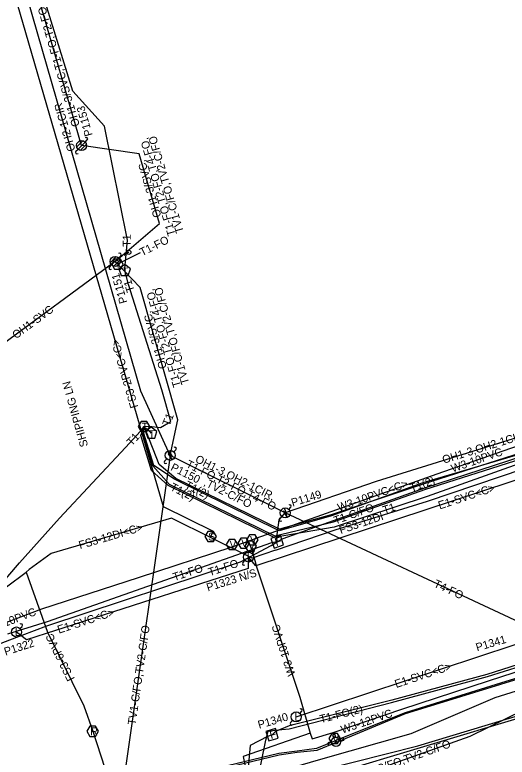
# Model space of a CAD drawing. Extents: x 2336688 to 2352634, y 362473 to 369571.
# Drawn here: x 2346759.7 to 2347005.5, y 367179.3 to 367550.3 of the extents above; entities that cross this region are included whole.
import ezdxf

# ---------------------------------------------------------------- set-up
doc = ezdxf.new("R2010")
doc.units = 0
for name, color, linetype in [('RD_EX_DV_Prop', 7, 'Continuous'), ('RD_EX_DV_TX_Prop', 7, 'Continuous'), ('RD_EX_RW', 7, 'Continuous'), ('RD_EX_RW_TX', 7, 'Continuous'), ('RD_HC_Data_Tic', 7, 'Continuous'), ('RD_PD_CstnLmt', 7, 'Continuous'), ('RD_PD_Final_TrvlWay', 7, 'Continuous'), ('RD_PD_PatLn4', 7, 'Continuous'), ('RD_SHT_ShtClip', 7, 'Continuous'), ('RD_Sketch1', 7, 'Continuous'), ('RD_Sketch2', 7, 'Continuous'), ('RD_Sketch5', 7, 'Continuous'), ('RD_TX_Misc1', 7, 'Continuous')]:
    doc.layers.add(name, color=color, linetype=linetype)

# ---------------------------------------------------------------- blocks, each defined once
blk = doc.blocks.new('GW')
at = {"layer": 'RD_HC_Data_Tic'}
blk.add_line((0, 0), (0, 5), dxfattribs=at)
blk.add_circle((0, 0), 2, dxfattribs=at)

msp = doc.modelspace()

# ---------------------------------------------------------------- linework, layer by layer
at = {"layer": 'RD_EX_RW_TX'}
msp.add_line((2346913.35, 367169.48), (2347148.27, 367240), dxfattribs=at)
for points in [[(2346827.77, 367341.15), (2346827.34, 367341.7), (2346825.07, 367343.48), (2346824.21, 367344.56), (2346824.21, 367344.56), (2346826.62, 367344.73), (2346832.44, 367344.01), (2346837.57, 367347.11), (2346833.13, 367362.89), (2346816.44, 367415.45), (2346815.1, 367420.66), (2346814.52, 367422.45), (2346814.54, 367423.44), (2346815.97, 367437.64), (2346804.36, 367494.65), (2346788.63, 367512.17), (2346772.74, 367563.49)], [(2347493.21, 367479.93), (2347455.71, 367473.66), (2347452.74, 367474.1), (2347448.74, 367473.85), (2347412.51, 367459.94), (2347396.43, 367453.77), (2347382.64, 367448.58), (2347379.12, 367448.82), (2347347.7, 367441.05), (2347301.35, 367428.58), (2347253.11, 367413.66), (2347204.34, 367396.75), (2347168.08, 367381.62), (2347139.54, 367369.91), (2347109.42, 367360.33), (2347060.14, 367343.81), (2347012.82, 367329.5), (2346964.23, 367313.72), (2346893.43, 367288.42), (2346890.71, 367286.97), (2346887.9, 367286.45), (2346775.81, 367246.88), (2346756.05, 367240.68)], [(2347493.07, 367480.59), (2347455.62, 367474.3), (2347452.74, 367474.1), (2347450.17, 367472.02), (2347413.02, 367459.45), (2347396.97, 367451.28), (2347348.05, 367437.46), (2347302.76, 367423.98), (2347255.28, 367408.11), (2347207.74, 367387.96), (2347168.62, 367376.63), (2347134.49, 367365.89), (2347110.11, 367358.5), (2347060.95, 367341.47), (2347013.68, 367326.75), (2346965.57, 367309.6), (2346919.17, 367294.2), (2346889.18, 367289.05), (2346836.21, 367315.04), (2346827.9, 367322.52), (2346822.65, 367340.13), (2346824.21, 367344.56)], [(2347493.75, 367473.66), (2347444.81, 367465.06), (2347396.07, 367455.9), (2347345.96, 367442.69), (2347300.78, 367430.21), (2347252.72, 367414.9), (2347203.98, 367399.02), (2347167.78, 367385.01), (2347137.95, 367372.86), (2347109.32, 367361.19), (2347059.71, 367345.57), (2347012.57, 367330.88), (2346963.45, 367316.33), (2346917.8, 367299.85), (2346891.73, 367292.36), (2346839.33, 367318.15), (2346829.05, 367325.03), (2346824.09, 367341.03), (2346824.21, 367344.56)], [(2347493.77, 367474.07), (2347444.64, 367465.68), (2347395.98, 367456.43), (2347345.81, 367443.17), (2347300.67, 367430.69), (2347252.46, 367415.35), (2347204.25, 367399.86), (2347167.66, 367385.47), (2347137.74, 367373.17), (2347109.3, 367361.85), (2347059.64, 367346.11), (2347012.51, 367331.46), (2346963.58, 367315.78), (2346917.62, 367300.41), (2346891.78, 367293.28), (2346839.99, 367318.61), (2346831.68, 367325.52), (2346825.4, 367341.75), (2346824.21, 367344.56)], [(2346822.31, 367431.36), (2346811.94, 367426.18), (2346810.92, 367425.75), (2346809.69, 367427.05)], [(2346744.36, 367255.92), (2346762.03, 367276.39), (2346781.92, 367298.77), (2346814.85, 367333.98), (2346822.42, 367342.26), (2346824.21, 367344.56), (2346823.39, 367341.4), (2346828.52, 367324.89), (2346836.66, 367315.73), (2346889.46, 367289.94), (2346918.72, 367296.97), (2346964.46, 367313.14), (2347013.05, 367328.63), (2347060.47, 367342.93), (2347109.88, 367359.54), (2347134.28, 367367.62), (2347132.27, 367372.32), (2347131.88, 367373.69), (2347132.25, 367375.15), (2347127.72, 367400.1)], [(2346929.43, 366898.3), (2346926.24, 366950.27), (2346914.94, 366994.66), (2346903.95, 367048.72), (2346891.88, 367094.98), (2346882.43, 367148.75), (2346880.23, 367164.03), (2346885.05, 367187.76), (2346886.25, 367192.23), (2346889.58, 367192.85), (2346896.67, 367193.51), (2346947.77, 367206.59), (2346995.79, 367219.64), (2347046.69, 367235.53), (2347089.94, 367248.15), (2347136.19, 367262.43), (2347184.88, 367278.93), (2347230.19, 367297.47), (2347271.77, 367311.28), (2347325.01, 367320.63), (2347375.99, 367328.45), (2347424.9, 367338.06), (2347468.18, 367347.3), (2347525.21, 367359.4)], [(2346729.92, 367125.44), (2346760.09, 367132.46), (2346822.83, 367150.8), (2346847.92, 367159.43), (2346911.38, 367177.91), (2346957.67, 367191.14), (2346999.5, 367209.08), (2347049.12, 367224.56), (2347093.92, 367240.35), (2347120.7, 367252.77), (2347143.99, 367255.5), (2347186.71, 367269.91), (2347236.58, 367285.94), (2347255.06, 367289.24), (2347276.57, 367291.67), (2347281.58, 367292.99), (2347300.77, 367298.26), (2347328.04, 367305.43), (2347378.49, 367318.88), (2347428.36, 367324.58), (2347471.76, 367333.48), (2347528.47, 367342.27)], [(2346897.18, 367161.87), (2346897.33, 367167.15), (2346913.45, 367172.96), (2346960.85, 367184.91), (2347003.36, 367197.72), (2347054.81, 367213.14), (2347089.91, 367226.4), (2347147.29, 367244.91), (2347193.34, 367259.48), (2347243.62, 367272.38), (2347257.76, 367276.24), (2347278.69, 367281.44), (2347302.95, 367288.88), (2347331.85, 367293.13), (2347381.23, 367305.16), (2347429.75, 367317.72), (2347473.23, 367326.64), (2347527.97, 367334.66)], [(2346386.07, 367172.12), (2346435.22, 367175.26), (2346485.78, 367178.87), (2346532.3, 367185.17), (2346581.16, 367192.44), (2346634.62, 367203.07), (2346681.71, 367213.65), (2346729.26, 367227.27), (2346757.13, 367237.94), (2346775.57, 367244.97), (2346872.31, 367276.87), (2346887.68, 367285.05), (2346890.71, 367286.97), (2346890.49, 367289.26), (2346891.73, 367297.92), (2346894.69, 367301.37)], [(2347184.08, 367281.81), (2347138.56, 367267.72), (2347089.38, 367252.03), (2347046.03, 367236.73), (2346995.36, 367220.65), (2346947.88, 367207.83), (2346896.65, 367195.02), (2346889.86, 367192.06), (2346888.13, 367190.49), (2346885.89, 367189.55), (2346877.25, 367185.04), (2346875.24, 367162.99), (2346879.34, 367145.21), (2346889.15, 367095.18), (2346897.75, 367046.5), (2346908.64, 366996.35), (2346918.58, 366948.75), (2346927.75, 366898.93)], [(2347187.63, 367266.43), (2347137.4, 367253.23), (2347093.35, 367238.65), (2347047.24, 367230.28), (2346997.39, 367214.83), (2346954.54, 367201.39), (2346927.39, 367190.56), (2346910.36, 367183.58), (2346900.58, 367182.36), (2346891.43, 367181.19), (2346845.03, 367169.9), (2346819.99, 367162.67), (2346802.3, 367157.83), (2346797.35, 367156.24), (2346793.14, 367153.5), (2346783.01, 367146.37), (2346758.96, 367136.25)], [(2346759.16, 367135.67), (2346783.33, 367145.57), (2346793.56, 367152.89), (2346797.35, 367156.24), (2346802.42, 367157.05), (2346820.18, 367162.16), (2346845.16, 367169.26), (2346891.6, 367180.39), (2346900.69, 367181.78), (2346910.69, 367182.74), (2346927.88, 367189.94), (2346954.81, 367201.03), (2346997.5, 367214.34), (2347047.41, 367229.71), (2347093.48, 367238.02), (2347137.76, 367252.45), (2347187.57, 367265.92)]]:
    msp.add_lwpolyline(points, dxfattribs=at)
for points in [[(2346813.81, 367425.75), (2346812.37, 367428.25), (2346809.48, 367428.25), (2346808.04, 367425.75), (2346809.48, 367423.25), (2346812.37, 367423.25)], [(2346814.52, 367425.45), (2346811.67, 367423.38), (2346812.76, 367420.02), (2346816.28, 367420.02), (2346817.37, 367423.38)], [(2346827.1, 367344.56), (2346825.66, 367347.06), (2346822.77, 367347.06), (2346821.33, 367344.56), (2346822.77, 367342.06), (2346825.66, 367342.06)], [(2346827.77, 367344.15), (2346824.92, 367342.07), (2346826.01, 367338.72), (2346829.53, 367338.72), (2346830.62, 367342.07)], [(2346892.3, 367290.13), (2346887.56, 367288.56), (2346889.12, 367283.81), (2346893.87, 367285.38)], [(2346889.79, 367193.61), (2346885.01, 367192.15), (2346886.47, 367187.37), (2346891.25, 367188.83)]]:
    msp.add_lwpolyline(points, close=True, dxfattribs=at)
at = {"layer": 'RD_HC_Data_Tic'}
for p, q in [((2346790.59, 367484.3), (2346793.65, 367487.36)), ((2346791.23, 367483.18), (2346794.77, 367486.71)), ((2346794.77, 367486.71), (2346795.83, 367487.77)), ((2346790.17, 367482.11), (2346791.23, 367483.18)), ((2346792.35, 367482.53), (2346795.42, 367485.59)), ((2346807.27, 367426.4), (2346810.33, 367429.46)), ((2346807.92, 367425.28), (2346811.45, 367428.81)), ((2346809.04, 367424.63), (2346812.1, 367427.69)), ((2346811.45, 367428.81), (2346812.52, 367429.88)), ((2346806.86, 367424.22), (2346807.92, 367425.28)), ((2346839.05, 367331.88), (2346840.11, 367332.95)), ((2346834.46, 367327.29), (2346835.52, 367328.35)), ((2346896.46, 367303.14), (2346897.52, 367304.2)), ((2346891.86, 367298.54), (2346892.92, 367299.61)), ((2346878.11, 367281.07), (2346879.17, 367282.13)), ((2346873.51, 367276.47), (2346874.57, 367277.54)), ((2346762.2, 367243.61), (2346763.26, 367244.67)), ((2346901.94, 367201.18), (2346903, 367202.24)), ((2346897.34, 367196.59), (2346898.4, 367197.65))]:
    msp.add_line(p, q, dxfattribs=at)
for points in [[(2346836.89, 367332.13), (2346837.72, 367330.11), (2346836.26, 367330.91), (2346838.14, 367328.23), (2346838.14, 367328.23), (2346836.94, 367330.33), (2346838.32, 367329.53)], [(2346894.29, 367303.38), (2346895.12, 367301.37), (2346893.66, 367302.17), (2346895.54, 367299.49), (2346895.54, 367299.49), (2346894.34, 367301.58), (2346895.72, 367300.78)]]:
    msp.add_lwpolyline(points, close=True, dxfattribs=at)
for centre in [(2346793, 367484.94), (2346809.69, 367427.05), (2346837.29, 367330.12), (2346894.69, 367301.37), (2346876.34, 367279.3), (2346760.44, 367241.84), (2346900.17, 367199.42)]:
    msp.add_circle(centre, 2.5, dxfattribs=at)
for centre, start, end in [((2346795.3, 367488.3), 315, 135), ((2346790.7, 367481.58), 135, 315), ((2346811.99, 367430.41), 315, 135), ((2346807.39, 367423.69), 135, 315), ((2346839.58, 367333.48), 315, 135), ((2346834.99, 367326.76), 135, 315), ((2346896.99, 367304.73), 315, 135), ((2346892.39, 367298.01), 135, 315), ((2346878.64, 367282.66), 315, 135), ((2346874.04, 367275.94), 135, 315), ((2346762.73, 367245.2), 315, 135), ((2346902.47, 367202.77), 315, 135), ((2346897.87, 367196.06), 135, 315)]:
    msp.add_arc(centre, 0.75, start, end, dxfattribs=at)
at = {"layer": 'RD_PD_Final_TrvlWay'}
for points in [[(2347365.04, 367648.59), (2347375.04, 367646.81), (2347420.85, 367453.86), (2347411.66, 367432.11), (2347408.65, 367425.96), (2347247.09, 367389.8), (2347245.57, 367389.37), (2347243.03, 367393.87), (2347242.83, 367388.6), (2347145.71, 367361.39), (2347142.58, 367366.06), (2347142.34, 367360.37), (2347024.46, 367322.51), (2347021.03, 367327.02), (2347021.01, 367321.39), (2346880.04, 367274.9), (2346876.34, 367279.3), (2346876.12, 367273.62), (2346794.47, 367247.23), (2346765.54, 367237.88), (2346760.44, 367241.84)], [(2346900.17, 367199.42), (2347008.96, 367235.37), (2347049.36, 367249.06), (2347056.78, 367227.15), (2347058.34, 367224.76), (2347058.11, 367227.6), (2347050.69, 367249.51), (2347105.72, 367268.16), (2347228.62, 367304.26)]]:
    msp.add_lwpolyline(points, dxfattribs=at)
at = {"layer": 'RD_SHT_ShtClip'}
for p, q in [((2346793, 367484.94), (2346749.05, 367636.56)), ((2346809.69, 367427.05), (2346738.38, 367374.51)), ((2346837.29, 367330.12), (2346809.48, 367136.35)), ((2346894.69, 367301.37), (2346837.29, 367330.12)), ((2347058.34, 367224.76), (2346894.69, 367301.37))]:
    msp.add_line(p, q, dxfattribs=at)
for points in [[(2346837.29, 367330.12), (2346822.52, 367362.29), (2346753.65, 367601.46), (2346749.05, 367636.56)], [(2346809.69, 367427.05), (2346831.86, 367445.93), (2346821.82, 367480.76), (2346793, 367484.94)], [(2346837.29, 367330.12), (2346841.01, 367347.81), (2346822.17, 367413.97), (2346809.69, 367427.05)], [(2347135.6, 367376.27), (2347089.3, 367363.5), (2346940.06, 367317.1), (2346894.69, 367301.37)], [(2346809.48, 367136.35), (2346886.82, 367154.19), (2346987.08, 367189.8), (2347058.34, 367224.76)]]:
    msp.add_lwpolyline(points, dxfattribs=at)
at = {"layer": 'RD_Sketch2'}
for p, q in [((2346880.2, 367288.69), (2346970.59, 367320.92)), ((2346919.46, 367190.72), (2346918.36, 367190.36)), ((2346918.36, 367190.36), (2346918.82, 367188.96)), ((2346919.93, 367189.3), (2346919.46, 367190.72)), ((2346917.72, 367186.93), (2346916.01, 367186.37)), ((2346916.01, 367186.37), (2346916.37, 367185.27)), ((2346916.37, 367185.27), (2346918.04, 367185.82)), ((2346923.69, 367188.9), (2346921.92, 367188.32)), ((2346922.33, 367187.23), (2346924.05, 367187.8)), ((2346924.05, 367187.8), (2346923.69, 367188.9))]:
    msp.add_line(p, q, dxfattribs=at)
for points in [[(2346907.18, 367191.36), (2346908.2, 367188.48), (2346918.67, 367191.57), (2346952.96, 367203.21), (2346996.26, 367217.42), (2347046.54, 367233.83), (2347089.24, 367248.48), (2347137.8, 367263.72), (2347185.19, 367277.87), (2347233.41, 367292.66), (2347283.51, 367309.44), (2347303.65, 367314.93), (2347326.25, 367319.14), (2347377.74, 367324.63), (2347405.39, 367327.95), (2347438.97, 367330.87), (2347470.35, 367337.23), (2347531.2, 367351.47)], [(2346970.59, 367320.92), (2347011.15, 367335.04)], [(2346386.09, 367179.42), (2346434.89, 367182.46), (2346485.2, 367186.56), (2346529.45, 367192.27), (2346544.39, 367194.22), (2346581.43, 367201.55), (2346629.82, 367212.48), (2346678.58, 367223.4), (2346728.01, 367238.02), (2346741.1, 367241.32), (2346773.19, 367253.5), (2346821.4, 367269.08), (2346868.26, 367284.43), (2346876.19, 367287.27), (2346880.2, 367288.69)], [(2346876.19, 367287.27), (2346877.95, 367283.11), (2346880.48, 367273.94), (2346901.92, 367209.32), (2346907.18, 367191.36)], [(2346907.18, 367191.36), (2346873.77, 367179.55), (2346874.94, 367172.89), (2346883.31, 367148.26), (2346906.9, 367059.09), (2346929.73, 366951.1), (2346935.93, 366895.33), (2346950.72, 366767.23), (2346956.21, 366700.28)]]:
    msp.add_lwpolyline(points, dxfattribs=at)
for points in [[(2346881.2, 367287.88), (2346879.76, 367290.38), (2346876.87, 367290.38), (2346875.43, 367287.88), (2346876.87, 367285.38), (2346879.76, 367285.38)], [(2346870.98, 367285.64), (2346869.54, 367288.13), (2346866.65, 367288.13), (2346865.21, 367285.64), (2346866.65, 367283.14), (2346869.54, 367283.14)], [(2346876.85, 367286.22), (2346875.4, 367288.72), (2346872.52, 367288.72), (2346871.07, 367286.22), (2346872.52, 367283.72), (2346875.4, 367283.72)], [(2346880.31, 367284.8), (2346878.86, 367287.3), (2346875.98, 367287.3), (2346874.53, 367284.8), (2346875.98, 367282.3), (2346878.86, 367282.3)], [(2346922.32, 367188.64), (2346920.88, 367191.14), (2346917.99, 367191.14), (2346916.55, 367188.64), (2346917.99, 367186.14), (2346920.88, 367186.14)]]:
    msp.add_lwpolyline(points, close=True, dxfattribs=at)
for radius in [2.31, 0.289]:
    msp.add_circle((2346920.03, 367186.99), radius, dxfattribs=at)
for start, end in [(92.5081, 121.4753), (181.6013, 210.5776), (5.9475, 34.9239)]:
    msp.add_arc((2346920.03, 367186.99), 2.31, start, end, dxfattribs=at)
at = {"layer": 'RD_Sketch5'}
for points in [[(2346620.75, 368191.93), (2346579.58, 368179.97), (2346833.73, 367304.59), (2346858.75, 367292.23), (2346857.22, 367289.15)], [(2346889.8, 367282.74), (2346919.7, 367292.87), (2346965.73, 367307.3), (2347014.03, 367323.63), (2347062.01, 367339.53), (2347111.01, 367356.83), (2347134.82, 367365.07), (2347159.13, 367371.92), (2347205.14, 367395.36), (2347226.9, 367411.47), (2347251.72, 367417.37), (2347346.28, 367442.06), (2347396.34, 367454.61), (2347445.27, 367463.42), (2347494.44, 367469.25)], [(2346889.8, 367282.74), (2346878.18, 367278.8), (2346837.88, 367298.7), (2346777.8, 367281.05), (2346766.84, 367273.09)], [(2346599.88, 367264.44), (2346605.93, 367237.48), (2346609.58, 367221.28), (2346627.52, 367225.39), (2346678, 367242.45), (2346722.14, 367254.26), (2346755.51, 367264.46), (2346765.39, 367271.81), (2346766.84, 367273.09)], [(2346765.39, 367271.81), (2346776.02, 367241.77), (2346794.17, 367204.89), (2346798.54, 367192.2), (2346810.66, 367155.29), (2346821.32, 367118.37), (2346834.62, 367075.46), (2346843.34, 367041.99), (2346854.83, 366998.67), (2346869.3, 366936.93), (2346885.2, 366849.09), (2346899.13, 366743.03), (2346902.03, 366692.09)]]:
    msp.add_lwpolyline(points, dxfattribs=at)
for points in [[(2346860.31, 367289.55), (2346858.87, 367292.05), (2346855.98, 367292.05), (2346854.53, 367289.55), (2346855.98, 367287.05), (2346858.87, 367287.05)], [(2346801.43, 367192.2), (2346799.98, 367194.7), (2346797.09, 367194.7), (2346795.65, 367192.2), (2346797.09, 367189.69), (2346799.98, 367189.69)]]:
    msp.add_lwpolyline(points, close=True, dxfattribs=at)

# ---------------------------------------------------------------- block references
at = {"layer": 'RD_HC_Data_Tic', "xscale": 0.5546771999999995, "yscale": 0.5546771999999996, "rotation": 123.7242247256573}
msp.add_blockref('GW', (2346816.51, 367431.63), dxfattribs=at)

# ---------------------------------------------------------------- texts
at = {"layer": 'RD_EX_DV_Prop'}
for rotation, p in [(18.2511, (2346971.85, 367303.07)), (17.9118, (2346781.65, 367240.99)), (18.2901, (2346950.12, 367213.82))]:
    msp.add_text('E1-SVC<C>', height=4, rotation=rotation, dxfattribs=at).set_placement(p)
at = {"layer": 'RD_EX_DV_TX_Prop'}
for s, rotation, p in [('P1153', 106.1679, (2346798.58, 367490.24)), ('P1151', 105.8933, (2346815.91, 367406.61)), ('P1150', 333.401, (2346837.11, 367322.88)), ('P1149', 17.269, (2346898.41, 367304.45)), ('P1323 N/S', 17.269, (2346856.09, 367262.07)), ('P1322', 17.9118, (2346755.04, 367229.99)), ('P1341', 16.3203, (2346990.53, 367232.13)), ('P1340', 16.3203, (2346881.69, 367193.43))]:
    msp.add_text(s, height=4, rotation=rotation, dxfattribs=at).set_placement(p)
at = {"layer": 'RD_EX_RW'}
for s, rotation, p in [('T1', 90.6268, (2346817.6, 367434.37)), ('T1-FO', 26.5695, (2346823.23, 367429.59)), ('T1', 107.6175, (2346819.53, 367412.33)), ('T1', 68.4782, (2346836.88, 367344.41)), ('T1', 47.5504, (2346818.07, 367334.54)), ('T1(2)', 18.7092, (2346957.76, 367311.83)), ('T1(2)', 333.8575, (2346836.88, 367312.93)), ('T1(2)', 333.7952, (2346844.18, 367313.99)), ('T1-C/FO', 19.4599, (2346919.77, 367295.54)), ('T1', 18.3653, (2346944.18, 367300.71)), ('T1-FO', 18.2493, (2346839.32, 367267.28)), ('T1-FO', 18.2493, (2346857.01, 367269.72)), ('T1-FO(2)', 14.3576, (2346912.47, 367196.27))]:
    msp.add_text(s, height=4, rotation=rotation, dxfattribs=at).set_placement(p)
at = {"layer": 'RD_EX_RW_TX'}
for p in [(2346809.71, 367423.87), (2346813.29, 367420.22), (2346823, 367342.68), (2346826.54, 367338.92)]:
    msp.add_text('T', height=3.75, dxfattribs=at).set_placement(p)
for rotation, p in [(18.2493, (2346890.26, 367284.71)), (16.9682, (2346887.63, 367188.25))]:
    msp.add_text('F', height=4, rotation=rotation, dxfattribs=at).set_placement(p)
at = {"layer": 'RD_HC_Data_Tic'}
for p in [(2346875.53, 367277.37), (2346759.62, 367239.91), (2346899.36, 367197.48)]:
    msp.add_text('L', height=4, rotation=360, dxfattribs=at).set_placement(p)
at = {"layer": 'RD_PD_CstnLmt'}
for s, rotation, p in [('W3-10PVC', 19.1221, (2346978.34, 367321.53)), ('W3-10PVC<C>', 19.625, (2346921.63, 367302.02)), ('W3-10PVC', 20.7825, (2346745.68, 367240.92)), ('W3-10PVC', 107.9225, (2346899.84, 367220.56)), ('W3-12PVC', 18.7371, (2346923.27, 367191.02))]:
    msp.add_text(s, height=4, rotation=rotation, dxfattribs=at).set_placement(p)
at = {"layer": 'RD_PD_PatLn4'}
for s, rotation, p in [('OH1-3/SVC,T1-FO,T2-FO,T4-FO,TV1-C/FO,TV2-C/FO', 106.1679, (2346792.16, 367495.05)), ('OH2-1CIR', 106.0638, (2346789.98, 367482.64)), ('T1-FO,T2-FO,T4-FO,', 106.0764, (2346840, 367440.43)), ('TV1-C/FO,TV2-C/FO', 106.0764, (2346844.07, 367441.85)), ('OH1-3/SVC,', 106.0764, (2346832.88, 367449.6)), ('T1-FO,T2-FO,T4-FO,', 105.8932, (2346842.72, 367364.79)), ('TV1-C/FO,TV2-C/FO', 105.8932, (2346846.79, 367366.19)), ('OH1-SVC', 36.382, (2346760.24, 367388.13)), ('OH1-3/SVC,', 105.8932, (2346835.63, 367373.98)), ('OH1-3,OH2-1CIR,T2-FO,TV2-C/FO', 17.269, (2346973.86, 367325.91)), ('OH1-3,OH2-1CIR,', 333.401, (2346849.37, 367326.97)), ('T1-FO,T2-FO,T4-FO', 333.401, (2346844.8, 367324.45)), (',TV2-C/FO', 333.401, (2346853.6, 367315.24)), ('T4-FO', 334.9119, (2346968.52, 367264.6)), ('TV1-C/FO,TV2-C/FO', 81.8339, (2346819.94, 367195.18)), ('OH1-3/SVC,TV1-C/FO,TV2-C/FO', 19.5577, (2346902.36, 367157.58))]:
    msp.add_text(s, height=4, rotation=rotation, dxfattribs=at).set_placement(p)
at = {"layer": 'RD_Sketch1'}
for s, rotation, p in [('FS3-2PVC<C>', 106.1895, (2346821.35, 367354.38)), ('FS3-12DI', 18.7219, (2346922.44, 367290.76)), ('FS3-12DI<C>', 16.3736, (2346792.24, 367283.2)), ('FS3-6PVC', 116.2097, (2346789.69, 367218.53))]:
    msp.add_text(s, height=4, rotation=rotation, dxfattribs=at).set_placement(p)
at = {"layer": 'RD_Sketch2'}
for p in [(2346877.11, 367286.01), (2346866.89, 367283.76), (2346872.75, 367284.34), (2346876.21, 367282.93), (2346918.22, 367186.77)]:
    msp.add_text('V', height=3.75, dxfattribs=at).set_placement(p)
at = {"layer": 'RD_Sketch5'}
for s, p in [('S', (2346856.19, 367287.55)), ('R', (2346797.31, 367190.2))]:
    msp.add_text(s, height=4, dxfattribs=at).set_placement(p)
at = {"layer": 'RD_TX_Misc1'}
msp.add_text('SHIPPING LN', height=4, rotation=105.6563, dxfattribs=at).set_placement((2346796.3, 367334.92))

doc.saveas('drawing.dxf')
